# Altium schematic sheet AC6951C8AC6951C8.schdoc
size 127 x 101 mm
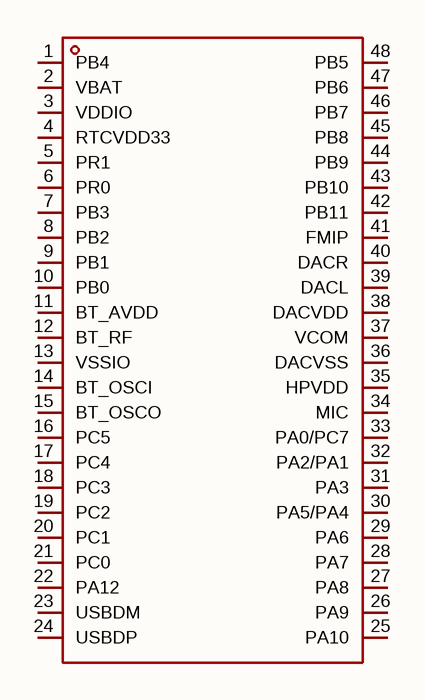
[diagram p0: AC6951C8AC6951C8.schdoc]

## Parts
U?  ac6951c8  [LQFP-48_L7.0-W7.0-P0.50-LS9.0-BL]  (value not drawn)

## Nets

Not connected (* = marked no-connect by the designer): U? 1(PB4) 2(VBAT) 3(VDDIO) 4(RTCVDD33) 5(PR1) 6(PR0) 7(PB3) 8(PB2) 9(PB1) 10(PB0) 11(BT_AVDD) 12(BT_RF) 13(VSSIO) 14(BT_OSCI) 15(BT_OSCO) 16(PC5) 17(PC4) 18(PC3) 19(PC2) 20(PC1) 21(PC0) 22(PA12) 23(USBDM) 24(USBDP) 25(PA10) 26(PA9) 27(PA8) 28(PA7) 29(PA6) 30(PA5/PA4) 31(PA3) 32(PA2/PA1) 33(PA0/PC7) 34(MIC) 35(HPVDD) 36(DACVSS) 37(VCOM) 38(DACVDD) 39(DACL) 40(DACR) 41(FMIP) 42(PB11) 43(PB10) 44(PB9) 45(PB8) 46(PB7) 47(PB6) 48(PB5)

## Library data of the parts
U? = ac6951c8: CPU内核:-;CPU最大主频:240MHz;CPU位数:32 Bit;; Manufacturer: JL(杰理); AddInBom: yes; ModelId: 093be70396ff421eb2cdb946d5311efc; ModelName: LQFP-48_L7.0-W7.0-H1.4-LS9.0-P0.50; ModelTransform: 354.331,354.331,0,0,0,0,0,0,0; CPU Maximum Speed: 240MHz; Core Size: 32 Bit; ADC (Bit): 16bit; Voltage - Supply: 2.2V~5.5V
